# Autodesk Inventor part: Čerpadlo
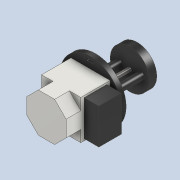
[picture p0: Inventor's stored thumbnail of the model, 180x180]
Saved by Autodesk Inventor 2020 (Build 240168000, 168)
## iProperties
Created: 2025-04
Part Number: Čerpadlo
Material: Ocel
Document SubType Name: Modeling
Designer: doma
Density: 7.85 g/cm^3
Appearance: Ocel
Mass: 3031.14 g
Surface Area: 1243.53 cm^2
Volume: 386.132 cm^3
Author: doma
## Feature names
1. Vysunutí1 [Extrusion]
2. Vysunutí2 [Extrusion]
3. Vysunutí3 [Extrusion]
4. Vysunutí4 [Extrusion]
5. Vysunutí7 [Extrusion]
6. Vysunutí13 [Extrusion]
7. Vysunutí14 [Extrusion]
8. Skořepina2
9. Vysunutí15 [Extrusion]
10. Tažení1
11. Vysunutí16 [Extrusion]
## Parameters: d1 = 15 mm, d2 = 0, d3 = 8 mm, d4 = 15 mm, d5 = 45 mm, d6 = 22.5 mm, d8 = 0, d9 = 125 mm, d11 = 0, d14 = 0, d20 = 0, d26 = 5.5 mm, d36 = 0, d38 = 6 mm, d39 = 0, d40 = 5 mm, d41 = 0, d42 = 0, d43 = -62.5 mm, d45 = 15 mm, d46 = 5 mm, d47 = 0, d48 = 0, d49 = 8 mm, d51 = 0
